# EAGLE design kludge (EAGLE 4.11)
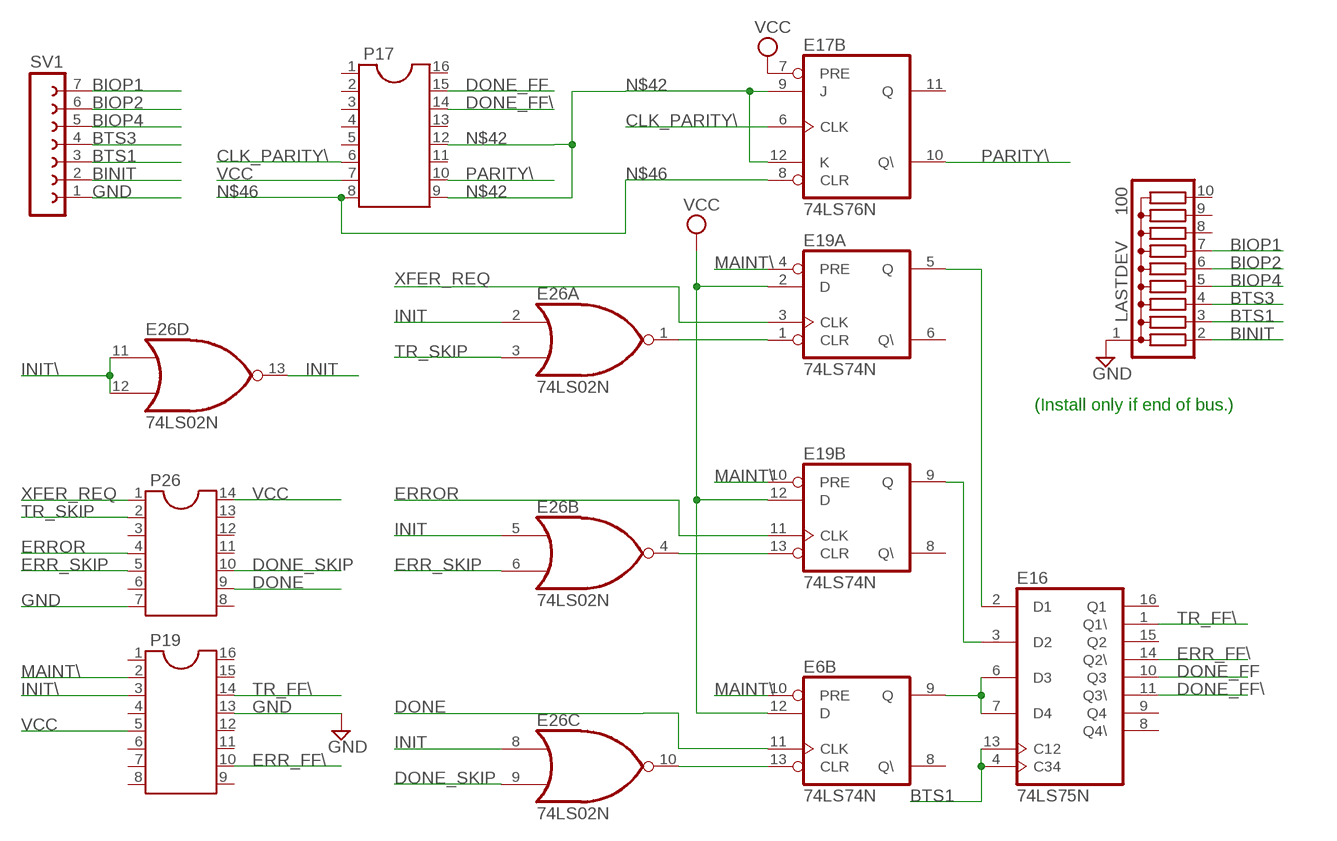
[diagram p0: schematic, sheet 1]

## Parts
E6  74LS74N  [DIL14]
E16  74LS75N  [DIL16]
E17  74LS76N  [DIL16]
E19  74LS74N  [DIL14]
E26  74LS02N  [DIL14]
LASTDEV  100  G09R  [SIL10]
P17  DIL16  [DIL16]
P19  DIL16  [DIL16]
P26  DIL14  [DIL14]
SV1  FE07-1  [FE07]

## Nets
BINIT: LASTDEV.2 SV1.2
BIOP1: LASTDEV.7 SV1.7
BIOP2: LASTDEV.6 SV1.6
BIOP4: LASTDEV.5 SV1.5
BTS1: E16.4(C34) E16.13(C12) LASTDEV.3 SV1.3
BTS3: LASTDEV.4 SV1.4
CLK_PARITY\: E17.6(B:CLK) P17.6
DONE: E6.11(B:CLK) P26.9
DONE_FF: E16.10(Q3) P17.15
DONE_FF\: E16.11(Q3\) P17.14
DONE_SKIP: E26.9(C:I1) P26.10
ERR_FF\: E16.14(Q2\) P19.10
ERR_SKIP: E26.6(B:I1) P26.5
ERROR: E19.11(B:CLK) P26.4
GND: LASTDEV.1 P19.13 P26.7 SV1.1
INIT: E26.2(A:I0) E26.5(B:I0) E26.8(C:I0) E26.13(D:O)
INIT\: E26.11(D:I0) E26.12(D:I1) P19.3
MAINT\: E6.10(B:PRE) E19.4(A:PRE) E19.10(B:PRE) P19.2
N$42: E17.9(B:J) E17.12(B:K) P17.9 P17.12
N$46: E17.8(B:CLR) P17.8
N$100: E16.2(D1) E19.5(A:Q)
N$103: E16.3(D2) E19.9(B:Q)
N$107: E6.9(B:Q) E16.6(D3) E16.7(D4)
N$108: E19.1(A:CLR) E26.1(A:O)
N$110: E19.13(B:CLR) E26.4(B:O)
N$111: E6.13(B:CLR) E26.10(C:O)
PARITY\: E17.10(B:Q\) P17.10
TR_FF\: E16.1(Q1\) P19.14
TR_SKIP: E26.3(A:I1) P26.2
VCC [supply]: E6.12(B:D) E17.7(B:PRE) E19.2(A:D) E19.12(B:D) P17.7 P19.5 P26.14
XFER_REQ: E19.3(A:CLK) P26.1
Unconnected: E6.1(A:CLR) E6.2(A:D) E6.3(A:CLK) E6.4(A:PRE) E6.5(A:Q) E6.6(A:Q\) E6.8(B:Q\) E16.8(Q4\) E16.9(Q4) E16.15(Q2) E16.16(Q1) E17.1(A:CLK) E17.2(A:PRE) E17.3(A:CLR) E17.4(A:J) E17.11(B:Q) E17.14(A:Q\) E17.15(A:Q) E17.16(A:K) E19.6(A:Q\) E19.8(B:Q\) LASTDEV.8 LASTDEV.9 LASTDEV.10 P17.1 P17.2 P17.3 P17.4 P17.5 P17.11 P17.13 P17.16 P19.1 P19.4 P19.6 P19.7 P19.8 P19.9 P19.11 P19.12 P19.15 P19.16 P26.3 P26.6 P26.8 P26.11 P26.12 P26.13

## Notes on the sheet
- (Install only if end of bus.)

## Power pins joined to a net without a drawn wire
GND: E6.7(P:GND) E16.12(GND) E17.13(P:GND) E19.7(P:GND) E26.7(P:GND)
VCC: E6.14(P:VCC) E16.5(VCC) E17.5(P:VCC) E19.14(P:VCC) E26.14(P:VCC)

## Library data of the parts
E6 E19 = 74xx-us:74*74: Dual D type positive edge triggered FLIP FLOP, preset and clear
E16 = 74xx-us:74*75: 4-bit bistable LATCH
E17 = 74xx-jameco:74*76: Dual J-K FLIP FLOP, preset and clear
E26 = 74xx-us:74*02: Quad 2-input NOR gate
LASTDEV = resistor-sil:G09R: SIL RESISTOR
P17 P19 = ic-package:DIL16: Dual In Line
P26 = ic-package:DIL14: Dual In Line
SV1 = con-lsta:FE07-1: FEMALE HEADER

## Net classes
1 supply: width 0.508 mm

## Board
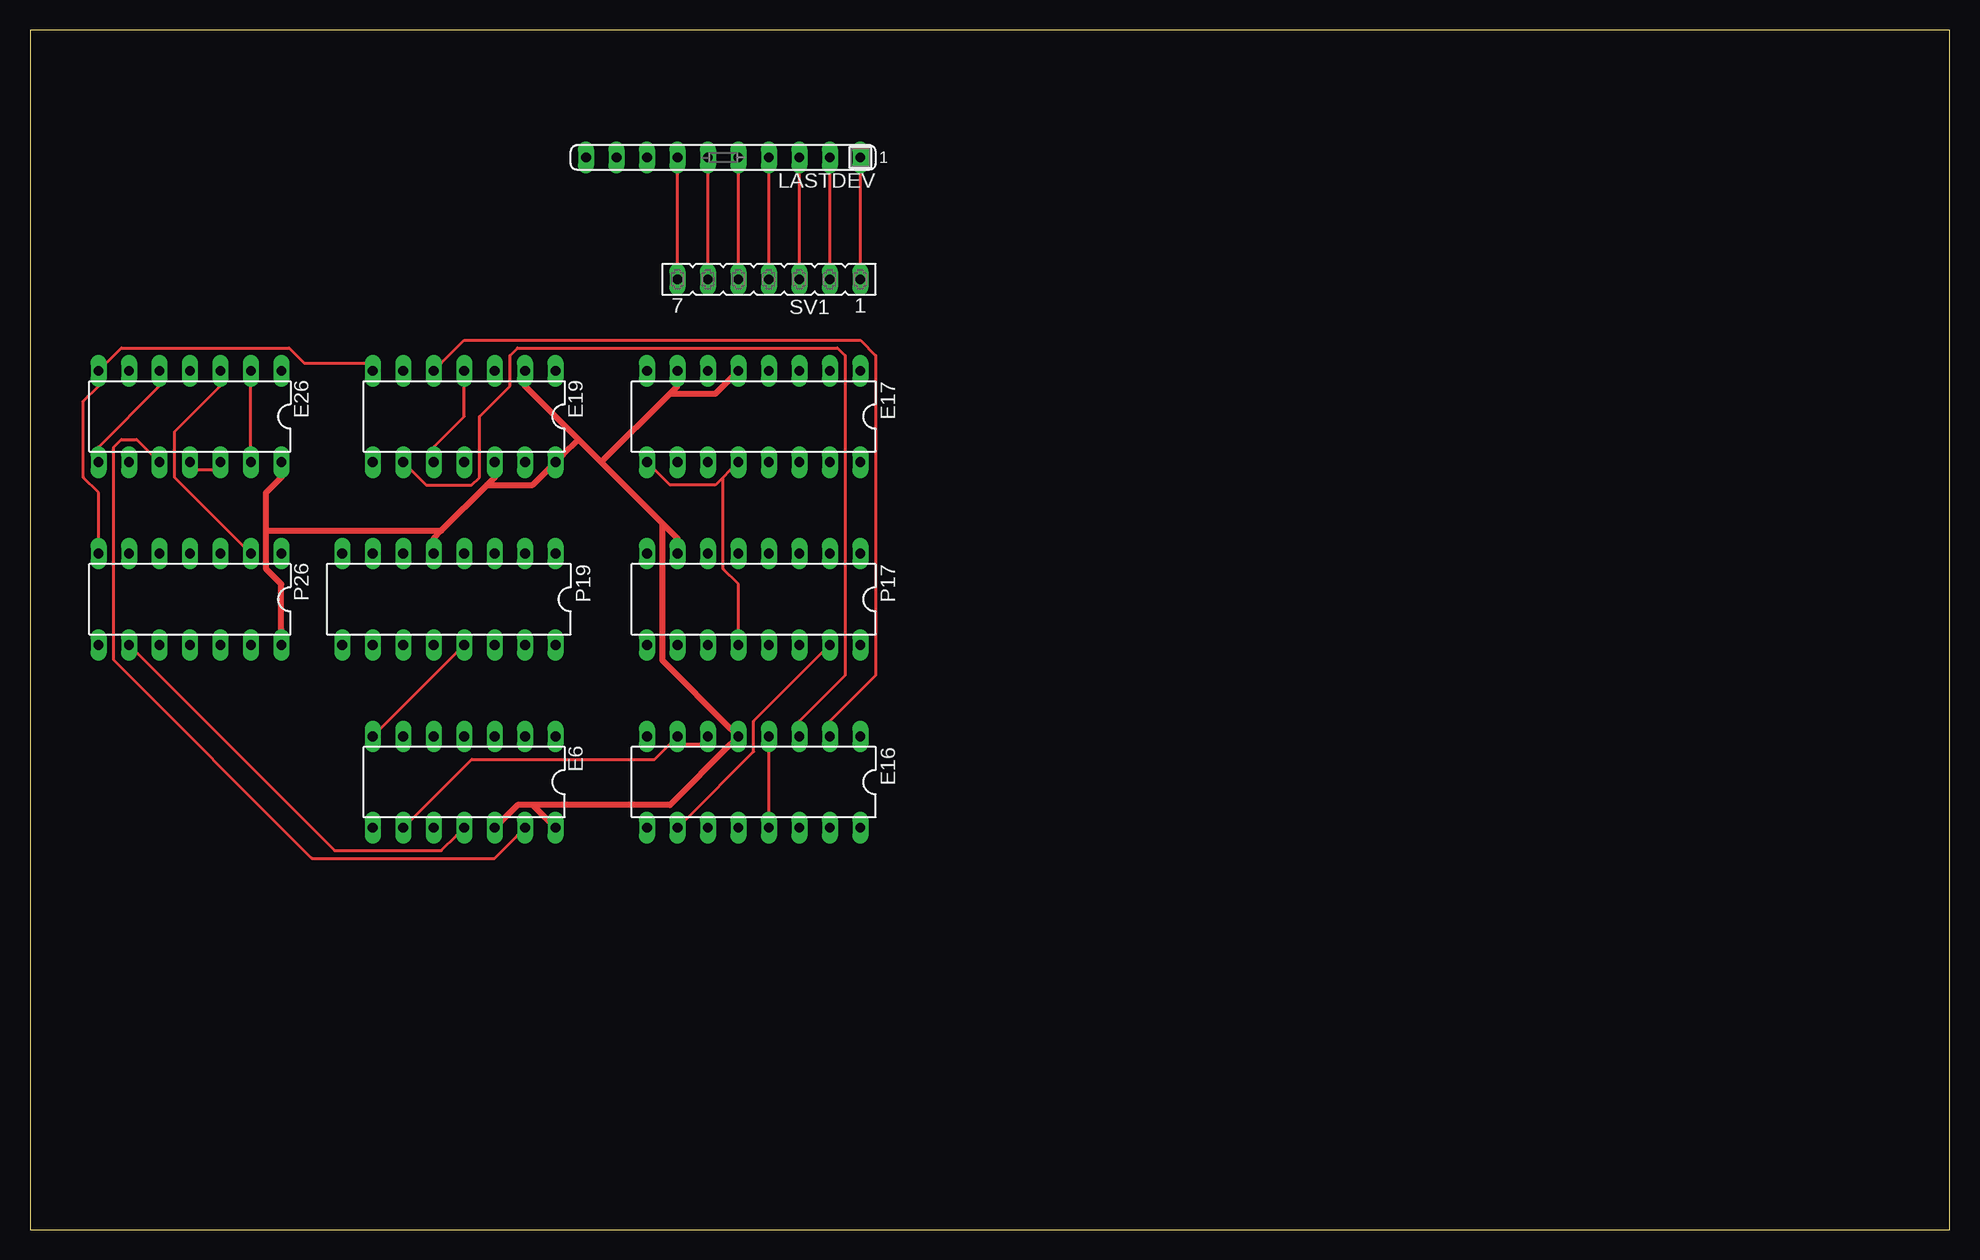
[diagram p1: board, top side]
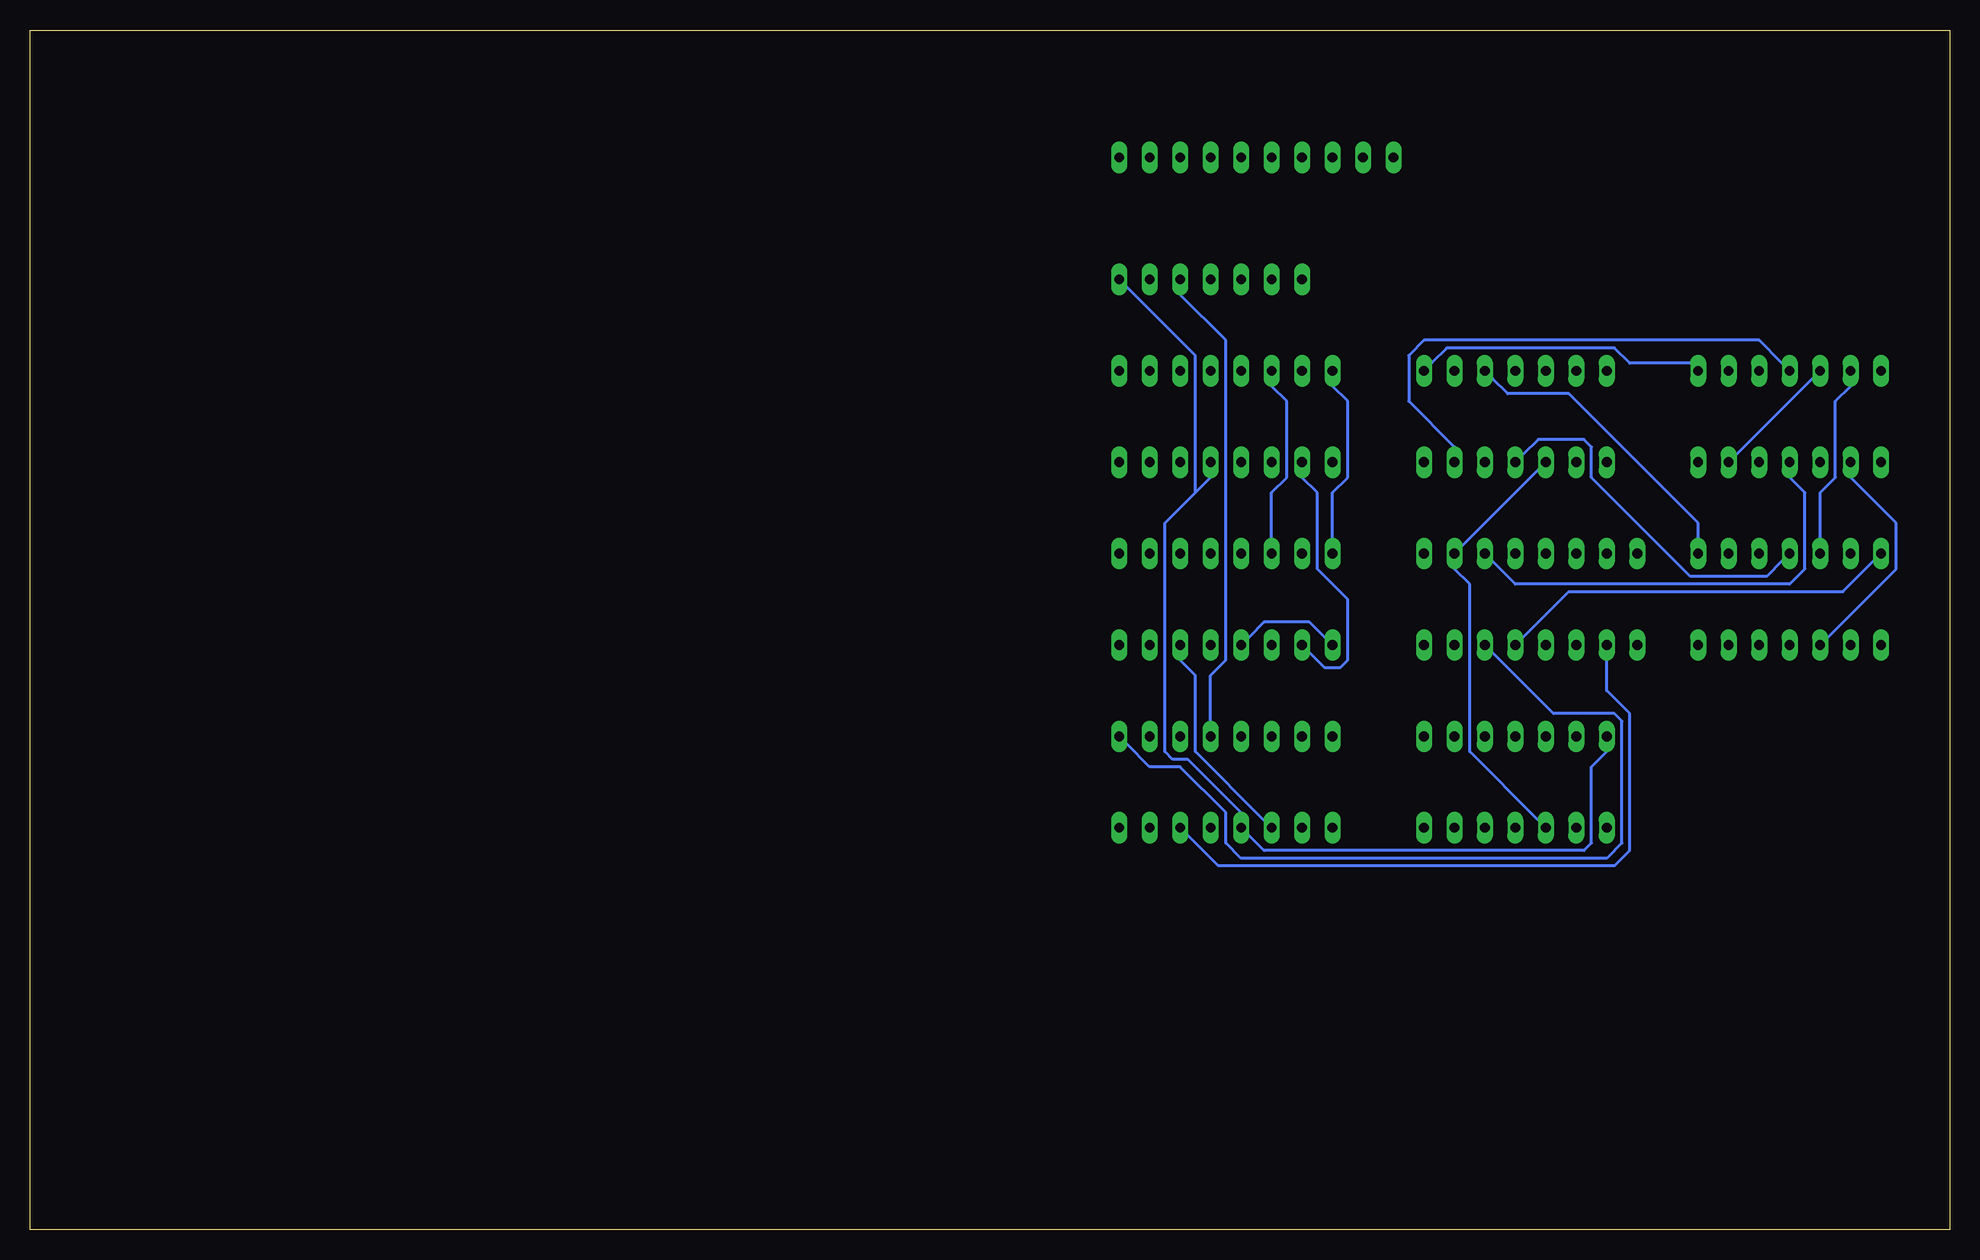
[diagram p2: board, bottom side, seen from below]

Size 160 x 100 mm. Coordinates in mm from the lower left corner, seen from the top.
Outline: 0,0 160,0 160,100 0,100 0,0
Copper layers (1*16): Top 0.035mm / dielectric 1.5mm / Bottom 0.035mm
Design rules "default": minimum track width 10mil, minimum drill 24mil, track to track 8mil, track to pad 8mil, pad to pad 8mil, via to via 8mil, smd to smd 8mil, copper to edge 40mil, drill to drill 8mil, minimum pad ring 10mil, minimum via ring 8mil, stop-mask expansion 4mil, vias tented up to drill 0mil, thermal gap 10mil

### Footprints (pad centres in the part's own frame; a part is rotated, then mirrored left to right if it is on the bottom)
DIL14 = drill 0.813 long: 1 -7.62,-3.81; 2 -5.08,-3.81; 3 -2.54,-3.81; 4 0,-3.81; 5 2.54,-3.81; 6 5.08,-3.81; 7 7.62,-3.81; 8 7.62,3.81; 9 5.08,3.81; 10 2.54,3.81; 11 0,3.81; 12 -2.54,3.81; 13 -5.08,3.81; 14 -7.62,3.81
DIL16 = drill 0.813 long: 1 -8.89,-3.81; 2 -6.35,-3.81; 3 -3.81,-3.81; 4 -1.27,-3.81; 5 1.27,-3.81; 6 3.81,-3.81; 7 6.35,-3.81; 8 8.89,-3.81; 9 8.89,3.81; 10 6.35,3.81; 11 3.81,3.81; 12 1.27,3.81; 13 -1.27,3.81; 14 -3.81,3.81; 15 -6.35,3.81; 16 -8.89,3.81
SIL10 = drill 0.813 long: 1 -11.43,0; 2 -8.89,0; 3 -6.35,0; 4 -3.81,0; 5 -1.27,0; 6 1.27,0; 7 3.81,0; 8 6.35,0; 9 8.89,0; 10 11.43,0
FE07 = drill 0.813 long: 1 -7.62,0; 2 -5.08,0; 3 -2.54,0; 4 0,0; 5 2.54,0; 6 5.08,0; 7 7.62,0

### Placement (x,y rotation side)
E6  36.19,37.3 180 top
E16  60.32,37.3 180 top
E17  60.32,67.78 180 top
E19  36.19,67.78 180 top
E26  13.33,67.78 180 top
LASTDEV  57.78,89.37 180 top
P17  60.32,52.54 180 top
P19  34.92,52.54 180 top
P26  13.33,52.54 180 top
SV1  61.59,79.21 180 top

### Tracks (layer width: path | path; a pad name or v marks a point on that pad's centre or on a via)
BINIT
  Top 0.254: SV1.2 66.67,80.48 66.67,88.1 LASTDEV.2
BIOP1
  Top 0.254: SV1.7 53.97,80.48 53.97,88.1 LASTDEV.7
BIOP2
  Top 0.254: SV1.6 56.51,80.48 56.51,88.1 LASTDEV.6
BIOP4
  Top 0.254: SV1.5 59.05,80.48 59.05,88.1 LASTDEV.5
BTS1
  Top 0.254: E16.13 61.59,34.76 61.59,39.84 E16.4 | SV1.3 64.13,80.48 64.13,88.1 LASTDEV.3
  Bottom 0.254: E16.4 61.59,42.38 61.59,46.19 60.32,47.46 60.32,74.13 64.13,77.94 SV1.3
BTS3
  Top 0.254: SV1.4 61.59,80.48 61.59,88.1 LASTDEV.4
CLK_PARITY\
  Bottom 0.254: P17.6 56.51,57.62 56.51,61.43 55.24,62.7 55.24,69.05 56.51,70.32 E17.6
DONE
  Top 0.254: P26.9 8.89,48.09 25.39,31.58 34.29,31.58 35.55,32.85 E6.11
DONE_FF
  Top 0.254: E16.10 54.61,34.12 60.32,39.84 60.32,42.38 66.03,48.09 P17.15
DONE_FF\
  Bottom 0.254: E16.11 57.15,34.12 62.86,39.84 62.86,46.19 64.13,47.46 P17.14
DONE_SKIP
  Bottom 0.254: P26.10 10.16,49.37 4.44,55.08 4.44,58.89 8.25,62.7 E26.9
ERR_FF\
  Bottom 0.254: P19.10 28.57,47.46 28.57,44.92 26.66,43.02 26.66,31.58 27.93,30.31 60.96,30.31 63.5,32.85 E16.14
ERR_SKIP
  Bottom 0.254: P26.5 10.79,57.62 10.79,61.43 9.52,62.7 9.52,69.05 8.25,70.32 E26.6
ERROR
  Bottom 0.254: P26.4 13.97,55.71 15.24,54.45 21.58,54.45 29.84,62.7 29.84,65.24 30.47,65.88 34.29,65.88 35.55,64.61 E19.11
GND
  Top 0.254: E6.7 29.2,41.74 35.55,48.09 P19.13 | P26.7 5.71,57.62 5.71,61.43 4.44,62.7 4.44,69.05 5.71,70.32 E26.7 6.34,72.22 7.62,73.5 21.58,73.5 22.86,72.22 27.93,72.22 E19.7 | SV1.1 69.21,80.48 69.21,88.1 LASTDEV.1
  Bottom 0.254: 62.86,61.43 65.4,58.89 65.4,39.84 64.77,39.2 63.5,39.2 59.05,34.76 E16.12 58.41,32.85 57.15,31.58 30.47,31.58 29.84,32.22 29.84,38.57 28.57,39.84 E6.7 | 62.86,61.43 61.59,62.7 E17.13 | P19.13 35.55,49.37 31.74,53.17 8.89,53.17 6.34,55.71 P26.7 | 62.86,61.43 62.86,72.86 68.57,78.58 SV1.1
INIT
  Top 0.254: E26.13 18.41,65.24 18.41,70.32 E26.2 | E26.8 5.71,65.24 10.79,70.32 E26.5
  Bottom 0.254: E26.13 17.77,64.61 11.43,70.95 E26.5
INIT\
  Top 0.254: E26.11 13.97,63.34 15.24,63.34 E26.12
  Bottom 0.254: P19.3 38.1,55.71 36.19,53.81 13.33,53.81 12.06,55.08 12.06,61.43 13.33,62.7 E26.11
MAINT\
  Top 0.254: E19.4 36.19,70.32 36.19,67.78 33.65,65.24 E19.10
  Bottom 0.254: E6.10 34.29,34.12 40,39.84 40,53.81 41.27,55.08 P19.2 40.64,56.98 34.29,63.34 E19.10
N$42
  Top 0.254: 57.78,62.7 58.41,63.34 E17.12 | 57.78,62.7 57.15,62.06 53.34,62.06 52.07,63.34 E17.9 | 57.78,62.7 57.78,55.08 59.05,53.81 59.05,50 P17.12
  Bottom 0.254: P17.9 52.07,49.37 53.34,50.63 57.15,50.63 58.41,49.37 P17.12
N$46
  Bottom 0.254: P17.8 51.43,57.62 51.43,61.43 50.16,62.7 50.16,69.05 51.43,70.32 E17.8
N$100
  Top 0.254: E19.5 34.29,72.22 36.19,74.13 69.21,74.13 70.48,72.86 70.48,46.19 66.67,42.38 E16.2
N$103
  Top 0.254: E19.9 31.74,63.34 33.02,62.06 36.83,62.06 37.46,62.7 37.46,67.78 40,70.32 40,72.86 40.64,73.5 67.3,73.5 67.94,72.86 67.94,46.19 64.13,42.38 E16.3
N$107
  Top 0.254: E6.9 31.74,34.12 36.83,39.2 52.07,39.2 53.34,40.48 E16.7 54.61,40.48 55.88,40.48 E16.6
N$108
  Bottom 0.254: E26.1 21.58,72.22 26.66,72.22 27.93,73.5 41.91,73.5 43.18,72.22 E19.1
N$110
  Bottom 0.254: E26.4 13.97,72.22 15.87,74.13 43.81,74.13 45.08,72.86 45.08,69.05 41.27,65.24 E19.13
N$111
  Top 0.254: E26.10 10.16,64.61 8.89,65.88 7.62,65.88 6.98,65.24 6.98,47.46 23.49,30.95 38.73,30.95 40.64,32.85 E6.13
PARITY\
  Bottom 0.254: P17.10 53.34,48.09 52.07,46.82 50.8,46.82 50.16,47.46 50.16,52.54 52.7,55.08 52.7,61.43 53.97,62.7 E17.10
TR_FF\
  Bottom 0.254: P19.14 38.1,48.09 33.02,43.02 27.93,43.02 27.3,42.38 27.3,32.22 28.57,30.95 59.05,30.95 60.32,32.22 60.32,34.76 64.13,38.57 66.67,38.57 68.57,40.48 E16.1
TR_SKIP
  Top 0.254: P26.2 17.77,56.98 12.06,62.7 12.06,66.51 15.87,70.32 E26.3
VCC
  Top 0.508: 19.68,58.25 19.68,61.43 20.95,62.7 E26.14 | 19.68,58.25 19.68,55.08 20.95,53.81 20.95,50 P26.14 | 38.1,62.06 38.73,62.7 E19.12 | 34.29,58.25 38.1,62.06 | 34.29,58.25 33.65,57.62 P19.5 | 38.1,62.06 41.91,62.06 43.18,63.34 E19.14 44.45,64.61 45.72,65.88 | 19.68,58.25 34.29,58.25 | 41.91,35.39 40.64,35.39 39.37,34.12 E6.12 | 41.91,35.39 43.18,34.12 E6.14 | 41.91,35.39 53.34,35.39 58.41,40.48 E16.5 58.41,41.74 52.7,47.46 52.7,58.89 | 45.72,65.88 41.27,70.32 E19.2 | 45.72,65.88 47.62,63.97 | 47.62,63.97 52.7,58.89 | 52.7,58.89 53.97,57.62 P17.7 | 47.62,63.97 53.34,69.69 | 53.34,69.69 53.97,70.32 E17.7 | 53.34,69.69 57.15,69.69 58.41,70.95 E17.5
XFER_REQ
  Bottom 0.254: P26.1 20.95,57.62 20.95,58.89 31.74,69.69 36.83,69.69 38.1,70.95 E19.3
